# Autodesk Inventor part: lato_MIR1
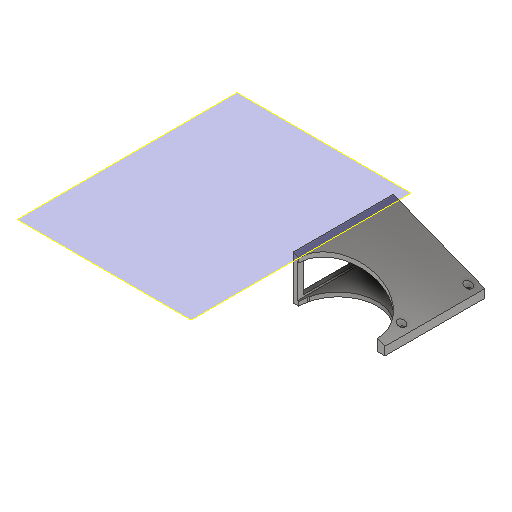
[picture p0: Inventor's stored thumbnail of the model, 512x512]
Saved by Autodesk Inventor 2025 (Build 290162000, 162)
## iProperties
Created: 2025-05
Part Number: lato_MIR1
Material: Plastica PET
Document SubType Name: Modeling
Designer: R5800u
Density: 1.541 g/cm^3
Appearance: Policarbonato - Trasparente
Author: R5800u
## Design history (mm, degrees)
derived "lato.ipt"
  sketch "Schizzo1"
    geometry: L1 (0, 0)-(-190, 0) reference; L2 (-190, 0)-(-190, 5) reference; L3 (0, 5)-(-190, 5) reference; L4 (0, 0)-(0, 5) reference; L5 (-300, -48)-(-300, -53) reference; L6 (-300, -48)-(-300, -38) reference; L7 (-300, -38)-(-190, 5) reference; L8 (-190, 5)-(-190, -48) reference; L9 (-190, -48)-(-300, -48) reference; L10 (-195, -2.323)-(-295, -41.414) reference; L11 (-295, -41.414)-(-295, -43) reference; L12 (-295, -43)-(-195, -43) reference; L13 (-195, -43)-(-195, -2.323) reference; L14 (-284, -37.114)-(-284, -43) reference
  sketch "Schizzo2"
    geometry: L1 (0, 53)-(0, 0) reference; L2 (0, 53)-(120, 53) reference; L3 (120, 0)-(120, 53) reference; L4 (0, 0)-(120, 0) reference; L5 (112.5, 45.5)-(7.5, 45.5) reference; L6 (7.5, 45.5)-(7.5, 7.5) reference; L7 (7.5, 7.5)-(112.5, 7.5) reference; L8 (112.5, 7.5)-(112.5, 45.5) reference; 1 further point
  sketch "Schizzo3"
    geometry: L1 (-81.5, -69.5)-(-81.5, -61.5) reference; L2 (-93.5, -69.5)-(-81.5, -69.5) reference; L3 (-93.5, -61.5)-(-93.5, -69.5) reference; L4 (-81.5, -61.5)-(-93.5, -61.5) reference; L5 (-93.5, 61.5)-(-81.5, 61.5) reference; L6 (-81.5, 61.5)-(-81.5, 69.5) reference; L7 (-81.5, 69.5)-(-93.5, 69.5) reference; 1 further point
  sketch "Schizzo4"
    geometry: L1 (0, -120)-(-110, -120) reference; L2 (-100, -120)-(-100, 0) reference; L3 (0, 0)-(-110, 0) reference; L4 (-100, -60)-(-110, -60) reference; L5 (-110, 0)-(-110, -120) reference; L6 (-100, -10)-(-10, -10) reference; L7 (0, 0)-(0, -120) reference; 6 further points
  node "Piano di lavoro1"
  node "Piano di lavoro2"
feature "Solido1::lato.ipt"
tag "Lavorazione contrassegno1"
sketch "Schizzo6"
  geometry: C1 r 2.25 at (-95, 90) reference; C2 r 2.25 at (-95, 10) reference; 1 further point
sketch "Schizzo8"
  geometry: L1 (0, -148.74)-(0, -92.562) reference; L2 (0, -148.74)-(0, -200.951) reference; L3 (0, -205)-(0, -95) reference; A1 r 45 centre (0, -148.74) between (-0.743, -193.734) and (-0.743, -103.747) reference; A2 r 47 centre (0, -148.74) between (-0.776, -195.734) and (-0.776, -101.747) reference; 1 further point
node "Solido1"
